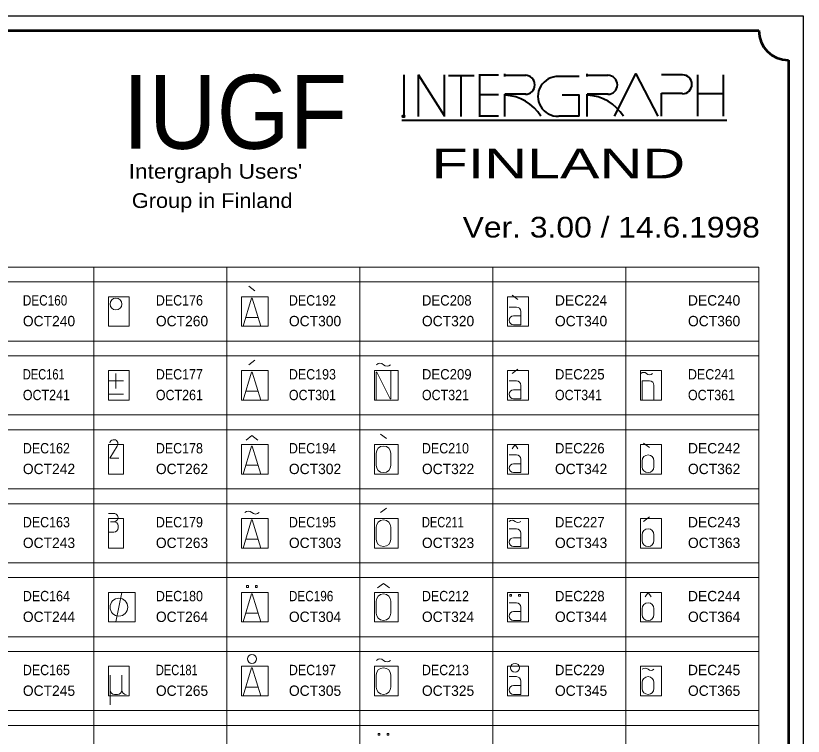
# Model space of a CAD drawing. Extents: x -200 to 7300, y -200 to 4800.
# Drawn here: x 4636 to 7300, y 2364 to 4800 of the extents above; entities that cross this region are included whole.
import ezdxf
from ezdxf.enums import TextEntityAlignment as Align

# ---------------------------------------------------------------- set-up
doc = ezdxf.new("R2010")
doc.units = 0
doc.header["$LTSCALE"] = 14
doc.header["$PDMODE"] = 32
doc.header["$PDSIZE"] = 7
for name, color, linetype, lineweight in [('1', 7, 'Continuous', 13), ('5', 7, 'Continuous', 40), ('6', 7, 'Continuous', 13), ('63', 7, 'Continuous', 13)]:
    doc.layers.add(name, color=color, linetype=linetype, lineweight=lineweight)
doc.layers.add('10', color=7, linetype='Continuous')
doc.layers.add('11', color=7, linetype='Continuous')

msp = doc.modelspace()

# ---------------------------------------------------------------- linework, layer by layer
at = {"layer": '1'}
for p, q in [((5445, 3870), (5425, 3885)), ((6335, 3840), (6315, 3855)), ((6305, 3815), (6330, 3815)), ((6320, 3785), (6345, 3785)), ((5414, 3780), (5456, 3780)), ((5425, 3620), (5445, 3635)), ((6315, 3590), (6335, 3605)), ((4975, 3540), (4975, 3590)), ((4950, 3565), (5000, 3565)), ((6305, 3565), (6330, 3565)), ((6795, 3550), (6795, 3500)), ((4950, 3520), (5000, 3520)), ((5414, 3530), (5456, 3530)), ((6320, 3535), (6345, 3535)), ((5890, 3370), (5870, 3385)), ((6780, 3340), (6760, 3355)), ((5855, 3320), (5855, 3280)), ((5905, 3320), (5905, 3280)), ((6305, 3315), (6330, 3315)), ((5414, 3280), (5456, 3280)), ((6320, 3285), (6345, 3285)), ((6755, 3295), (6755, 3275)), ((6795, 3295), (6795, 3275)), ((4968, 3117), (4950, 3117)), ((5870, 3120), (5890, 3135)), ((6760, 3090), (6780, 3105)), ((4968, 3089), (4957, 3089)), ((4982, 3075), (4982, 3068)), ((5855, 3070), (5855, 3030)), ((5905, 3070), (5905, 3030)), ((6305, 3065), (6330, 3065)), ((4968, 3054), (4950, 3054)), ((6755, 3045), (6755, 3025)), ((6795, 3045), (6795, 3025)), ((5414, 3030), (5456, 3030)), ((6320, 3035), (6345, 3035)), ((4975, 2750), (4995, 2850)), ((5855, 2820), (5855, 2780)), ((5905, 2820), (5905, 2780)), ((6305, 2815), (6330, 2815)), ((5414, 2780), (5456, 2780)), ((6320, 2785), (6345, 2785)), ((6755, 2795), (6755, 2775)), ((6795, 2795), (6795, 2775)), ((4955, 2570), (4955, 2470)), ((4995, 2570), (4995, 2520)), ((5855, 2570), (5855, 2530)), ((5905, 2570), (5905, 2530)), ((6305, 2565), (6330, 2565)), ((6320, 2535), (6345, 2535)), ((6755, 2545), (6755, 2525)), ((6795, 2545), (6795, 2525)), ((4970, 2505), (4980, 2505)), ((5414, 2530), (5456, 2530))]:
    msp.add_line(p, q, dxfattribs=at)
for points in [[(5405, 3750), (5434, 3845), (5436, 3845), (5465, 3750)], [(6345, 3800), (6345, 3755), (6320, 3755)], [(5855, 3500), (5855, 3595), (5857, 3595), (5903, 3505), (5905, 3505), (5905, 3600)], [(5405, 3500), (5434, 3595), (5436, 3595), (5465, 3500)], [(6345, 3550), (6345, 3505), (6320, 3505)], [(6755, 3500), (6755, 3565), (6780, 3565)], [(5455, 3365), (5435, 3380), (5415, 3365)], [(4985, 3304), (4954, 3304), (4979.3, 3344.9)], [(5405, 3250), (5434, 3345), (5436, 3345), (5465, 3250)], [(6335, 3335), (6325, 3350), (6315, 3335)], [(6345, 3300), (6345, 3255), (6320, 3255)], [(5405, 3000), (5434, 3095), (5436, 3095), (5465, 3000)], [(6345, 3050), (6345, 3005), (6320, 3005)], [(5900, 2865), (5880, 2880), (5860, 2865)], [(5405, 2750), (5434, 2845), (5436, 2845), (5465, 2750)], [(6785, 2835), (6775, 2850), (6765, 2835)], [(6345, 2800), (6345, 2755), (6320, 2755)], [(5405, 2500), (5434, 2595), (5436, 2595), (5465, 2500)], [(6345, 2550), (6345, 2505), (6320, 2505)]]:
    msp.add_lwpolyline(points, dxfattribs=at)
for points in [[(5417, 2867), (5423, 2867), (5423, 2873), (5417, 2873)], [(5447, 2867), (5453, 2867), (5453, 2873), (5447, 2873)], [(6307, 2837), (6313, 2837), (6313, 2843), (6307, 2843)], [(6337, 2837), (6343, 2837), (6343, 2843), (6337, 2843)], [(5862, 2367), (5868, 2367), (5868, 2373), (5862, 2373)], [(5892, 2367), (5898, 2367), (5898, 2373), (5892, 2373)]]:
    msp.add_lwpolyline(points, close=True, dxfattribs=at)
for centre, radius in [((4975, 3825), 20), ((4985, 2800), 30), ((5435, 2625), 15), ((6325, 2595), 15)]:
    msp.add_circle(centre, radius, dxfattribs=at)
for centre, radius, start, end in [((6330, 3800), 15, 0, 90), ((6320, 3770), 15, 90, 270), ((5868, 3608), 17, 45, 134.9981), ((5892, 3632), 17, 225, 314.9981), ((6760, 3580), 14.1, 45, 135), ((6780, 3600), 14.1, 225, 315), ((6330, 3550), 15, 0, 90), ((6780, 3550), 15, 0, 90), ((6320, 3520), 15, 90, 270), ((4967.5, 3352.5), 14, 327.0948, 165.9638), ((5880, 3320), 25, 0, 180), ((6330, 3300), 15, 0, 90), ((6775, 3295), 20, 0, 180), ((5880, 3280), 25, 180, 360), ((6320, 3270), 15, 90, 270), ((6775, 3275), 20, 180, 360), ((4968, 3103), 14, 265.8439, 90.0653), ((5423, 3108), 17, 45, 134.9981), ((5447, 3132), 17, 225, 314.9981), ((5880, 3070), 25, 0, 180), ((6315, 3080), 14.1, 45, 135), ((4968, 3075), 14, 0, 90), ((4968, 3068), 14, 270, 360), ((6335, 3100), 14.1, 225, 315), ((6330, 3050), 15, 0, 90), ((6775, 3045), 20, 0, 180), ((5880, 3030), 25, 180, 360), ((6320, 3020), 15, 90, 270), ((6775, 3025), 20, 180, 360), ((5880, 2820), 25, 0, 180), ((6330, 2800), 15, 0, 90), ((6775, 2795), 20, 0, 180), ((5880, 2780), 25, 180, 360), ((6320, 2770), 15, 90, 270), ((6775, 2775), 20, 180, 360), ((5868, 2608), 17, 45, 134.9981), ((5892, 2632), 17, 225, 314.9981), ((5880, 2570), 25, 0, 180), ((6765, 2580), 14.1, 45, 135), ((6785, 2600), 14.1, 225, 315), ((6330, 2550), 15, 0, 90), ((6775, 2545), 20, 0, 180), ((6320, 2520), 15, 90, 270), ((4970, 2520), 15, 180, 270), ((4980, 2520), 15, 270, 0), ((5010, 2520), 15, 180, 270), ((5880, 2530), 25, 180, 360), ((6775, 2525), 20, 180, 360)]:
    msp.add_arc(centre, radius, start, end, dxfattribs=at)
at = {"layer": '5', "lineweight": 53}
for p, q in [((-50, 4750), (7150, 4750)), ((7250, 4650), (7250, -50))]:
    msp.add_line(p, q, dxfattribs=at)
at = {"layer": '5'}
for p, q in [((5950, 4459), (5950, 4600)), ((5998, 4459), (5998, 4600)), ((5999, 4462), (5999, 4600)), ((6086, 4462), (5999, 4600)), ((6086, 4459), (6086, 4600)), ((6100, 4598), (6187, 4598)), ((6143, 4459), (6143, 4600)), ((6203, 4600), (6269, 4600)), ((6205, 4600), (6205, 4460)), ((6290, 4595), (6290, 4604)), ((6361, 4598), (6290, 4598)), ((6542, 4595), (6473, 4595)), ((6569, 4595), (6569, 4604)), ((6640, 4598), (6569, 4598)), ((6892, 4600), (6821, 4600)), ((6943, 4460), (6943, 4600)), ((7030, 4460), (7030, 4600)), ((6203, 4534), (6269, 4534)), ((6361, 4535), (6290, 4535)), ((6290, 4459), (6290, 4535)), ((6640, 4535), (6569, 4535)), ((6569, 4459), (6569, 4535)), ((6821, 4460), (6821, 4538)), ((6892, 4537), (6821, 4537)), ((6944, 4537), (7027, 4537)), ((6203, 4462), (6269, 4462)), ((6542, 4460), (6473, 4460)), ((5942, 4447), (7042, 4447))]:
    msp.add_line(p, q, dxfattribs=at)
at = {"layer": '5', "lineweight": 25}
msp.add_lwpolyline([(-200, -200), (-200, 4800), (7300, 4800), (7300, -200)], close=True, dxfattribs=at)
at = {"layer": '5'}
for points in [[(6662, 4460), (6734, 4604), (6808, 4460)], [(6662, 4460), (6734, 4604), (6808, 4460)], [(6542, 4460), (6542, 4531), (6485, 4531)]]:
    msp.add_lwpolyline(points, dxfattribs=at)
at = {"layer": '5', "lineweight": 53}
msp.add_arc((7250.2, 4750.2), 100.2, 180.1325, 269.8675, dxfattribs=at)
at = {"layer": '5'}
for centre, radius, start, end in [((6359.9, 4566.5), 32.1, 270, 90), ((6469.5, 4527.3), 67.1, 87.5556, 272.4444), ((6639.2, 4566.5), 32.1, 270, 90), ((6891.3, 4568.2), 32.1, 270, 90), ((6282.9, 4378.1), 153.8, 32.3885, 87.0195), ((6562.1, 4378.1), 153.8, 32.3885, 87.0195)]:
    msp.add_arc(centre, radius, start, end, dxfattribs=at)
msp.add_point((5948, 4460), dxfattribs=at)
at = {"layer": '6'}
for p, q in [((-50, 3950), (7150, 3950)), ((4900, 3950), (4900, -50)), ((5350, 3950), (5350, -50)), ((5800, 3950), (5800, -50)), ((6250, 3950), (6250, -50)), ((6700, 3950), (6700, -50)), ((7150, 3950), (7150, -50)), ((-50, 3900), (7150, 3900)), ((-50, 3700), (7150, 3700)), ((-50, 3650), (7150, 3650)), ((-50, 3450), (7150, 3450)), ((-50, 3400), (7150, 3400)), ((-50, 3200), (7150, 3200)), ((-50, 3150), (7150, 3150)), ((-50, 2950), (7150, 2950)), ((-50, 2900), (7150, 2900)), ((-50, 2700), (7150, 2700)), ((-50, 2650), (7150, 2650)), ((-50, 2450), (7150, 2450)), ((-50, 2400), (7150, 2400))]:
    msp.add_line(p, q, dxfattribs=at)
at = {"layer": '63'}
for points in [[(4950, 3750), (5020, 3750), (5020, 3850), (4950, 3850)], [(5400, 3750), (5490, 3750), (5490, 3850), (5400, 3850)], [(6300, 3750), (6370, 3750), (6370, 3850), (6300, 3850)], [(4950, 3500), (5020, 3500), (5020, 3600), (4950, 3600)], [(5400, 3500), (5490, 3500), (5490, 3600), (5400, 3600)], [(5850, 3500), (5930, 3500), (5930, 3600), (5850, 3600)], [(6300, 3500), (6370, 3500), (6370, 3600), (6300, 3600)], [(6750, 3500), (6820, 3500), (6820, 3600), (6750, 3600)], [(4950, 3250), (5000, 3250), (5000, 3350), (4950, 3350)], [(5400, 3250), (5490, 3250), (5490, 3350), (5400, 3350)], [(5850, 3250), (5930, 3250), (5930, 3350), (5850, 3350)], [(6300, 3250), (6370, 3250), (6370, 3350), (6300, 3350)], [(6750, 3250), (6820, 3250), (6820, 3350), (6750, 3350)], [(4950, 3000), (5000, 3000), (5000, 3100), (4950, 3100)], [(5400, 3000), (5490, 3000), (5490, 3100), (5400, 3100)], [(5850, 3000), (5930, 3000), (5930, 3100), (5850, 3100)], [(6300, 3000), (6370, 3000), (6370, 3100), (6300, 3100)], [(6750, 3000), (6820, 3000), (6820, 3100), (6750, 3100)], [(4950, 2750), (5040, 2750), (5040, 2850), (4950, 2850)], [(5400, 2750), (5490, 2750), (5490, 2850), (5400, 2850)], [(5850, 2750), (5930, 2750), (5930, 2850), (5850, 2850)], [(6300, 2750), (6370, 2750), (6370, 2850), (6300, 2850)], [(6750, 2750), (6820, 2750), (6820, 2850), (6750, 2850)], [(4950, 2500), (5020, 2500), (5020, 2600), (4950, 2600)], [(5400, 2500), (5490, 2500), (5490, 2600), (5400, 2600)], [(5850, 2500), (5930, 2500), (5930, 2600), (5850, 2600)], [(6300, 2500), (6370, 2500), (6370, 2600), (6300, 2600)], [(6750, 2500), (6820, 2500), (6820, 2600), (6750, 2600)]]:
    msp.add_lwpolyline(points, close=True, dxfattribs=at)

# ---------------------------------------------------------------- texts
at = {"layer": '10'}
for s, width, p in [('DEC160', 0.85, (4660, 3820)), ('DEC176', 0.9, (5110, 3820)), ('DEC192', 0.9, (5560, 3820)), ('DEC208', 0.95, (6010, 3820)), ('DEC161', 0.8, (4660, 3570)), ('DEC177', 0.9, (5110, 3570)), ('DEC193', 0.9, (5560, 3570)), ('DEC209', 0.95, (6010, 3570)), ('DEC225', 0.95, (6460, 3570)), ('DEC241', 0.9, (6910, 3570)), ('DEC162', 0.9, (4660, 3320)), ('DEC178', 0.9, (5110, 3320)), ('DEC194', 0.9, (5560, 3320)), ('DEC210', 0.9, (6010, 3320)), ('DEC226', 0.95, (6460, 3320)), ('DEC163', 0.9, (4660, 3070)), ('DEC179', 0.9, (5110, 3070)), ('DEC195', 0.9, (5560, 3070)), ('DEC211', 0.8, (6010, 3070)), ('DEC227', 0.95, (6460, 3070)), ('DEC164', 0.9, (4660, 2820)), ('DEC180', 0.9, (5110, 2820)), ('DEC196', 0.85, (5560, 2820)), ('DEC212', 0.9, (6010, 2820)), ('DEC228', 0.95, (6460, 2820)), ('DEC165', 0.9, (4660, 2570)), ('DEC181', 0.8, (5110, 2570)), ('DEC197', 0.9, (5560, 2570)), ('DEC213', 0.9, (6010, 2570)), ('DEC229', 0.95, (6460, 2570))]:
    msp.add_text(s, height=35, dxfattribs=dict(at, width=width)).set_placement(p)
for s, p in [('DEC224', (6460, 3820)), ('DEC240', (6910, 3820)), ('DEC242', (6910, 3320)), ('DEC243', (6910, 3070)), ('DEC244', (6910, 2820)), ('DEC245', (6910, 2570))]:
    msp.add_text(s, height=35, dxfattribs=at).set_placement(p)
at = {"layer": '11'}
for s, p in [('OCT240', (4660, 3750)), ('OCT260', (5110, 3750)), ('OCT300', (5560, 3750)), ('OCT320', (6010, 3750)), ('OCT340', (6460, 3750)), ('OCT360', (6910, 3750)), ('OCT242', (4660, 3250)), ('OCT262', (5110, 3250)), ('OCT302', (5560, 3250)), ('OCT322', (6010, 3250)), ('OCT342', (6460, 3250)), ('OCT362', (6910, 3250)), ('OCT243', (4660, 3000)), ('OCT263', (5110, 3000)), ('OCT303', (5560, 3000)), ('OCT323', (6010, 3000)), ('OCT343', (6460, 3000)), ('OCT363', (6910, 3000)), ('OCT244', (4660, 2750)), ('OCT264', (5110, 2750)), ('OCT304', (5560, 2750)), ('OCT324', (6010, 2750)), ('OCT344', (6460, 2750)), ('OCT364', (6910, 2750)), ('OCT245', (4660, 2500)), ('OCT265', (5110, 2500)), ('OCT305', (5560, 2500)), ('OCT325', (6010, 2500)), ('OCT345', (6460, 2500)), ('OCT365', (6910, 2500))]:
    msp.add_text(s, height=35, dxfattribs=at).set_placement(p)
at = {"layer": '11', "width": 0.9}
for s, p in [('OCT241', (4660, 3500)), ('OCT261', (5110, 3500)), ('OCT301', (5560, 3500)), ('OCT321', (6010, 3500)), ('OCT341', (6460, 3500)), ('OCT361', (6910, 3500))]:
    msp.add_text(s, height=35, dxfattribs=at).set_placement(p)
at = {"layer": '5'}
for s, height, width, p in [('IUGF', 250, 0.95, (5377.5, 4350)), ('FINLAND', 100, 1.5, (6471.5, 4250)), ("Intergraph Users'", 50, 1.15, (5311.5, 4249)), ('Group in Finland', 50, 1.1, (5300.5, 4150))]:
    msp.add_text(s, height=height, dxfattribs=dict(at, width=width)).set_placement(p, align=Align.CENTER)
at = {"layer": '5', "width": 1.15}
msp.add_text('Ver. 3.00 / 14.6.1998', height=70, dxfattribs=at).set_placement((7153.3, 4050), align=Align.RIGHT)

doc.saveas('drawing.dxf')
